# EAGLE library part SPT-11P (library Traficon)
PHOENIX CONTACT type SPT 1.5/11-V-3.5
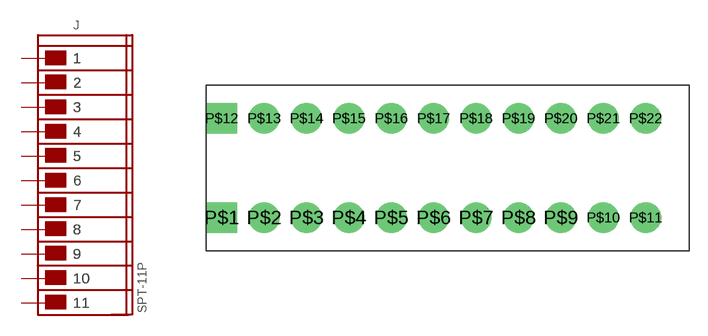
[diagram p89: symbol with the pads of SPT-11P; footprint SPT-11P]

Designator prefix J

## SPT-11P  [SPT-11P]
P$1  1
P$2  2
P$3  3
P$4  4
P$5  5
P$6  6
P$7  7
P$8  8
P$9  9
P$10  10
P$11  11
P$12  1
P$13  2
P$14  3
P$15  4
P$16  5
P$17  6
P$18  7
P$19  8
P$20  9
P$21  10
P$22  11

## Footprint SPT-11P (pad centres in mm)
drill 1.1 pad 2.54 square: P$1 0,0; P$12 0,8.2
drill 1.1 pad 2.54 round: P$2 3.5,0; P$3 7,0; P$4 10.5,0; P$5 14,0; P$6 17.5,0; P$7 21,0; P$8 24.5,0; P$9 28,0; P$10 31.5,0; P$11 35,0; P$13 3.5,8.2; P$14 7,8.2; P$15 10.5,8.2; P$16 14,8.2; P$17 17.5,8.2; P$18 21,8.2; P$19 24.5,8.2; P$20 28,8.2; P$21 31.5,8.2; P$22 35,8.2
